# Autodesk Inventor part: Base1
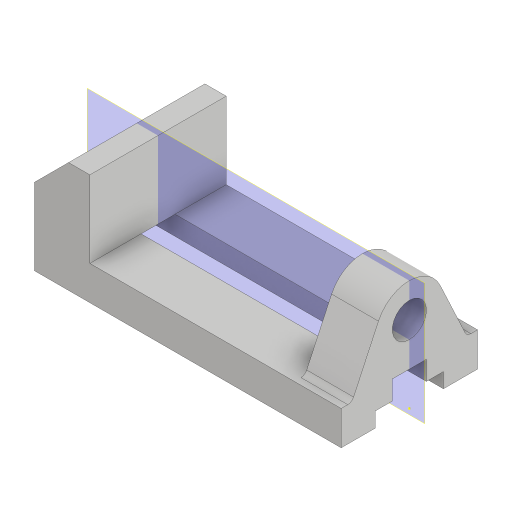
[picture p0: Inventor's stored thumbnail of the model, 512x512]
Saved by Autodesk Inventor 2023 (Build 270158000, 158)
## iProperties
Created: 2016-03
Part Number: Base1
Material: Generic
Document SubType Name: Modeling
Designer: Sandeep
Density: 1 g/cm^3
Appearance: Default
Author: Sandeep
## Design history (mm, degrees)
sketch "Sketch1"
  geometry: L1 (0, 0)-(0, 16); L2 (0, 16)-(118, 16); L3 (118, 16)-(118, 52); L4 (118, 52)-(144, 52); L5 (144, 52)-(144, 0); L6 (144, 0)-(0, 0)
  constraints: 12 end point, 3 perpendicular, 1 vertical
  dimensions: "d1" = 144 distance of L5.end L1.start; "d2" = 26 distance of L3.end L4.end; "d3" = 16 distance between parallel lines of L6 L2; "d4" = 36 distance between parallel lines of L2 L4
extrude "Extrusion1" new body sketch "Sketch1" stored distance "d5" = 64; taper "d6" = 0 deg
chamfer "Chamfer1" distance "d7" = 16; stored, may be unused: second distance "d8" = 16, angle "d9" = 45 deg
sketch "Sketch4"
  geometry: 1 further point
sketch "Sketch5"
  geometry: L1 (-16, 5.02)-(-42.762, 17.499); L2 (-42.762, 46.501)-(-16, 58.98); L3 (-52, 64)-(-52, 0) reference; L4 (-16, 32)-(-54.774, 32); L5 (-52, 64)-(-16, 64) reference; L6 (-16, 64)-(-16, 0) reference; L7 (-16, 5.02)-(-16, 58.98); L8 (0, 64)-(0, 0) reference; A1 r 16 centre (-36, 32) between (-42.762, 46.501) and (-42.762, 17.499); 1 further point
  constraints: 8 end point, 3 point on line, 3 tangent, 2 point on circle, 1 centre point, 1 collinear, 1 horizontal, 1 other
  dimensions: "d21" = 50 deg angle of L2 L1; "d22" = 36 distance from line of L8 A1.centre
extrude "Extrusion2" join sketch "Sketch5" distance "d23" = 22; taper "d24" = 0 deg
fillet "Fillet1" dims "d25" = 3
sketch "Sketch6"
  geometry: L1 (-36, 64)-(-36, 0) reference; C1 r 8 at (-36, 32); A1 r 16 centre (-36, 32) between (-42.762, 46.501) and (-42.762, 17.499) reference; 1 further point
  constraints: 1 centre point, 1 concentric, 1 midpoint
  dimensions: "d26" = 16 diameter of C1
extrude "Extrusion3" cut sketch "Sketch6" distance "d27" = 22; taper "d28" = 0 deg
sketch "Sketch7"
  geometry: L1 (0, 0)-(0, 64) reference; L2 (0, 16)-(-7, 16); L3 (-7, 16)-(-7, 24); L4 (-7, 24)-(-16, 24); L5 (-16, 3.109)-(-16, 60.891) reference; L6 (-16, 24)-(-16, 40); L7 (-7, 40)-(-7, 48); L8 (-7, 48)-(0, 48); L9 (0, 48)-(0, 16); L10 (-7, 40)-(-16, 40); L11 (-44, 32)-(-36, 32); 1 further point
  constraints: 18 end point, 6 point on line, 4 perpendicular, 2 horizontal, 1 collinear, 1 horizontal alignment, 4 other
  dimensions: "d29" = 32 distance between parallel lines of L2 L8; "d30" = 7 distance of L7.end L8.end; "d45" = 16 distance between parallel lines of L10 L4
extrude "Extrusion4" cut sketch "Sketch7" distance "d31" = 167.75; taper "d32" = 0 deg
sketch "Sketch8"
  geometry: L1 (144, 0)-(144, -16) reference; L2 (0, 0)-(144, 0) reference; L3 (0, -16)-(0, 0) reference; 3 further points
  dimensions: "d33" = 70 distance of point (108, -10) point (38, -10); "d35" = 10 distance from line of L2 point (108, -10); "d36" = 10 distance from line of L2 point (38, -10); "d46" = 38 distance from line of L3 point (38, -10)
hole "Hole1" sketch "Sketch8" at (38, -10), (108, -10) diameter "d37" = 4.917; stored, may be unused: countersink angle "d41" = 90 deg, drill point angle "d43" = 118 deg; dims "d38" = 12, "d39" = 4, "d40" = 2, "d42" = 10
workplane "Work Plane1"
mirror "Mirror1"
body "Solid1"
other parameters: "d10" = 16, "d13" = 7, "d14" = 16, "d44" = -32
